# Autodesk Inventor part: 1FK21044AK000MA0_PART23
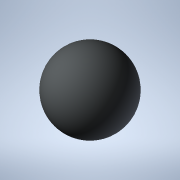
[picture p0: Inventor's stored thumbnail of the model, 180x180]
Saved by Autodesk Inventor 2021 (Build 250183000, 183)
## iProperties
Created: 2025-04
Part Number: 1FK21044AK000MA0_PART23
Material: Generic
Catalog Web Link: www.3dfindit.com
Description: -Servo synchronous motor
Document SubType Name: Modeling
Designer: psAdmin
Mass: 0.137258 g
Surface Area: 1.2868 cm^2
Volume: 0.137258 cm^3
Density: 1 g/cm^3
Appearance: PSOLRGB-212-217-219
Category: PARTsolutions
Title: 1FK21044AK000MA0_PART23
Author: Cadenas PARTsolutions
Comments: Servo synchronous motor
Sending System: PARTsolutions
Preprocessor: ST-DEVELOPER v19.3
PSOL_IDENT_0: {$CADENAS_DATA/23d-libs/siemens_ag/_cat_/87/f4/1fk21044ak000ma0.prj},216 {VTYP=3D},{NB=1FK21044AK000
PSOL_IDENT_1: MA0_PART23},{LINA=1FK21044AK000MA0_PART23},{NN=1FK21044AK000MA0_PART23},{NOPRJ=TRUE},{DATE=19.08.202
PSOL_IDENT_2: 5 14:00:48},{GEOMDATE=30.07.2025 02:00:50},{VERSION=},{LINEID=10},{WBVAR=},{WBNUMERIC=}  {NB=1FK2104
PSOL_IDENT_3: 4AK000MA0_PART23},{LINA=1FK21044AK000MA0_PART23},{KT=DUMMY},{PREVIEW=../../../_pool_/cb/72/p_d211_xx
PSOL_IDENT_4: _00434j.png},{DESCSHORT=SIMOTICS S-1FK2 HD, SINAMICS S210 3AC 400V-480V, 0.95 Nm, 6000 rpm},{DESCLON
PSOL_IDENT_5: G=SIMOTICS S-1FK2 HD servo motor M0=1.27 Nm; PN = 0.6 kW at nN=6000 rpm (380-480 V); PN = 0.4 kW at
PSOL_IDENT_6: nN=3000 rpm (200-240 V); degree of protection IP64; cylindrical shaft D19x40mm; absolute encoder 22-
PSOL_IDENT_7: bit + 12-bit multiturn (encoder AM22DQC); with OCC interface; plug size M17, rotatable; SIMOTICS S-1
PSOL_IDENT_8: FK2 servomotorfor a wide range of uses in industrial environments. SIMOTICS S‑1FK2 servomotors are c
PSOL_IDENT_9: ompact synchronous motors with a high dynamic performance that set themselves apart as a result of t
PSOL_IDENT_10: heir high power density, degree of protection and overload capability. The motors are available in t
PSOL_IDENT_11: wo variants: as High Dynamic variant (highest dynamic performance as a result of the low intrinsic m
PSOL_IDENT_12: oment of inertia for applications demanding a high dynamic performance with low moved masses) - and
PSOL_IDENT_13: as Compact variant (precise and stable closed-loop control for medium up to large moved masses as a
PSOL_IDENT_14: result of a medium intrinsic moment of inertia). SIMOTICSS‑1FK2 servomotors fully exploit their stre
PSOL_IDENT_15: ngths in a system with the SINAMICSS210 frequency converter and simple connection using the one cabl
PSOL_IDENT_16: e connection (OCC). Advantages include the short control and positioning times, fast and precise cor
PSOL_IDENT_17: rection of disturbing quantities as well as stable control with a high dynamic performance. The serv
PSOL_IDENT_18: o motors can be configured to address a wide range of requirements. For example with and without hol
PSOL_IDENT_19: ding brake, IP64 or IP65 degree of protection, singleturn or multiturn absolute encoders - to name j
PSOL_IDENT_20: ust a few. Further, the servomotors are available in different shaft heights extending from 20 to 10
PSOL_IDENT_21: 0. A shaft sealing ring is available to achieve an IP65 degree of protection and for subsequent moun
PSOL_IDENT_22: ting at the motor or as spare part. SIMOTICS - the optimum motor for each and every motion control a
PSOL_IDENT_23: pplication.},{INTNO=195125056312},{SUPPLIERALTNO=1FK2104-4AK00-0MA0},{MANUID=1FK21044AK000MA0},{MANU
PSOL_IDENT_24: NAME=Siemens},{MANUTYPEDESC=Synchronous motor 1FK2-HD 1,27 Nm},{AAU732=SIMOTICS},{AAO057=S-1FK2},{AA
PSOL_IDENT_25: U734=SIMOTICS S-1FK2 HD servo motor M0=1.27 Nm; PN = 0.6 kW at nN=6000 rpm (380-480 V); PN = 0.4 kW
PSOL_IDENT_26: at nN=3000 rpm (200-240 V); degree of protection IP64; cylindrical shaft D19x40mm; absolute encoder
PSOL_IDENT_27: 22-bit + 12-bit multiturn (encoder AM22DQC); with OCC interface; plug size M17, rotatable;},{AAW338=
PSOL_IDENT_28: Synchronous motor 1FK2-HD 1,27 Nm},{AAO742=SIMOTICS},{AAO663=4042948690994},{NOCUPEROU=1},{PRICEQUAN
PSOL_IDENT_29: TITY=1},{QUANTITYMIN=1},{QUANTITYINT=1},{CTN=85015100},{COO=DE},{AAO676=1FK2104-4AK00-0MA0},{AAO677=
PSOL_IDENT_30: Siemens AG},{ORDERUNIT=C62},{CONTENTUNIT=C62}
NB: 1FK21044AK000MA0_PART23
NT: Servo synchronous motor
NBSYN: $MANUID._PART23
LINA: 1FK21044AK000MA0_PART23
CATALOG: SIEMENS
PREVIEW: ../../../_pool_/cb/72/p_d211_xx_00434j.png
DESCSHORT: SIMOTICS S-1FK2 HD, SINAMICS S210 3AC 400V-480V, 0.95 Nm, 6000 rpm
DESCLONG: SIMOTICS S-1FK2 HD servo motor M0=1.27 Nm; PN = 0.6 kW at nN=6000 rpm (380-480 V); PN = 0.4 kW at nN=3000 rpm (200-240 V); degree of protection IP64; cylindrica
INTNO: 195125056312
SUPPLIERALTNO: 1FK2104-4AK00-0MA0
MANUID: 1FK21044AK000MA0
MANUNAME: Siemens
MANUTYPEDESC: Synchronous motor 1FK2-HD 1,27 Nm
AAU732: SIMOTICS
AAO057: S-1FK2
AAU734: SIMOTICS S-1FK2 HD servo motor M0=1.27 Nm; PN = 0.6 kW at nN=6000 rpm (380-480 V); PN = 0.4 kW at nN=3000 rpm (200-240 V); degree of protection IP64; cylindrica
AAW338: Synchronous motor 1FK2-HD 1,27 Nm
AAO742: SIMOTICS
AAO663: 4042948690994.0
NOCUPEROU: 1
PRICEQUANTITY: 1
QUANTITYMIN: 1
QUANTITYINT: 1
CTN: 85015100
COO: DE
ARTICLENO: 1FK21044AK000MA0_PART23
BOMINFO: 1FK21044AK000MA0_PART23
CREATOR: CADENAS GmbH
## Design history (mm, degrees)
feature "2025_04_17_15_37_40_0588"
body "Solid1"
